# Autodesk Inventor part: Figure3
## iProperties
Shininess: 77.0
Length Units: 11269
Angle Units: 11279
Time Units: 11290
Mass Units: 11283
Length Display Precision: 3
Angle Display Precision: 2
Created: 2001-12
Part Number: Figure3
Document SubType Name: Modeling
Designer: CADSoft
Density: 1 g/cm^3
Density: 0.0
Volumn: 0.0
Area: 0.0
PropertySet Name: Model Information
Control State: 0
Master: False
Checked Out: False
Author: CADSoft
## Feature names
1. Extrusion2
